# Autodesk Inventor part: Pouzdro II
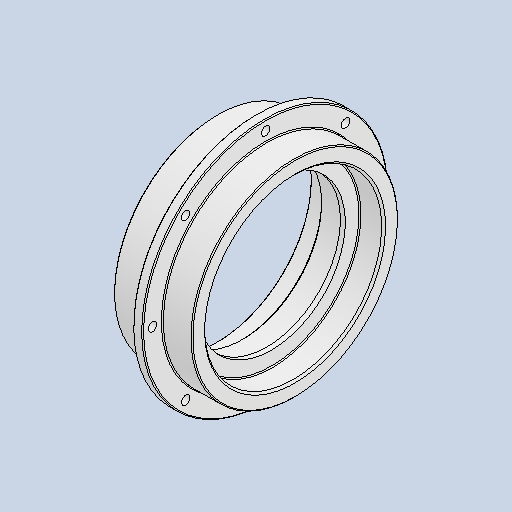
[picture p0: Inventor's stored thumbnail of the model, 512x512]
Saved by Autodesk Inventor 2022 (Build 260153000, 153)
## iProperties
Created: 2025-05
Part Number: Pouzdro II
Material: Všeobecné
Document SubType Name: Modeling
Designer: jbart
Density: 1 g/cm^3
Appearance: Hladká – bílá
Mass: 7788.21 g
Surface Area: 6273.05 cm^2
Volume: 7788.21 cm^3
Author: jbart
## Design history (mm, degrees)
sketch "Náčrt1"
  geometry: L1 (0, 0)-(110, 0); L2 (0, 160)-(52, 160); L3 (52, 160)-(52, 150); L4 (52, 150)-(62, 150); L5 (62, 150)-(62, 180); L6 (62, 180)-(110, 180); L7 (110, 180)-(110, 190); L8 (110, 190)-(110, 190); L9 (110, 190)-(110, 210); L10 (110, 210)-(50, 210); L11 (50, 210)-(50, 250); L12 (50, 250)-(30, 250); L13 (30, 250)-(30, 210); L14 (30, 210)-(0, 210); L15 (0, 190)-(0, 160); L16 (0, 210)-(-49, 210); L17 (-49, 210)-(-49, 190); L18 (-49, 190)-(0, 190); 2 further points
  constraints: 36 end point, 14 perpendicular, 3 horizontal, 3 point on line, 2 vertical alignment, 1 midpoint
  dimensions: "d0" = 110 distance of L1.start L1.end; "d1" = 320 diameter of L2 L1; "d2" = 360 diameter of L6 L1; "d3" = 380 diameter of L8 L1; "d4" = 52 distance of L2.start L2.end; "d5" = 48 distance of L5.end L6.end; "d6" = 10 distance of L3.end L4.end; "d7" = 20 distance of L11.end L12.end; "d8" = 30 distance of L13.end L14.end; "d9" = 300 diameter of L4 L1; "d14" = 420 diameter of L14 L1; "d15" = 500 diameter of L12 L1; "d18" = 49 distance of L14.end L16.end; "d19" = 20 distance of L16.end L17.end; "d20" = 30 distance from line of L1.start L13; "d37" = 49 distance from line of L17 L1.start (derived)
revolve "Rotace1" sketch "Náčrt1" stored, may be unused: angle "d10" = 90 deg
chamfer "Zkosení1" distance "d11" = 4; stored, may be unused: second distance "d12" = 2, angle "d13" = 45 deg
sketch "Náčrt2" dims "d16" = 460
  geometry: L1 (0, 0)-(0, 230); 2 further points
  constraints: 2 coincident, 2 end point, 1 vertical, 1 vertical alignment, 2 other
hole "Díra1" sketch "Náčrt2" at (0, 230) diameter "d21" = 17.5; stored, may be unused: countersink angle "d25" = 90 deg, drill point angle "d27" = 118 deg; dims "d22" = 6, "d23" = 20, "d24" = 12, "d26" = 8
pattern_circular "Kruhové pole1" dims angle "d29" = 360 deg
chamfer "Zkosení2" distance "d31" = 2; stored, may be unused: second distance "d32" = 2, angle "d33" = 45 deg
fillet "Zaoblení1" dims "d34" = 2
fillet "Zaoblení2" dims "d35" = 2
fillet "Zaoblení3" dims "d38" = 2
node "Těleso1"
